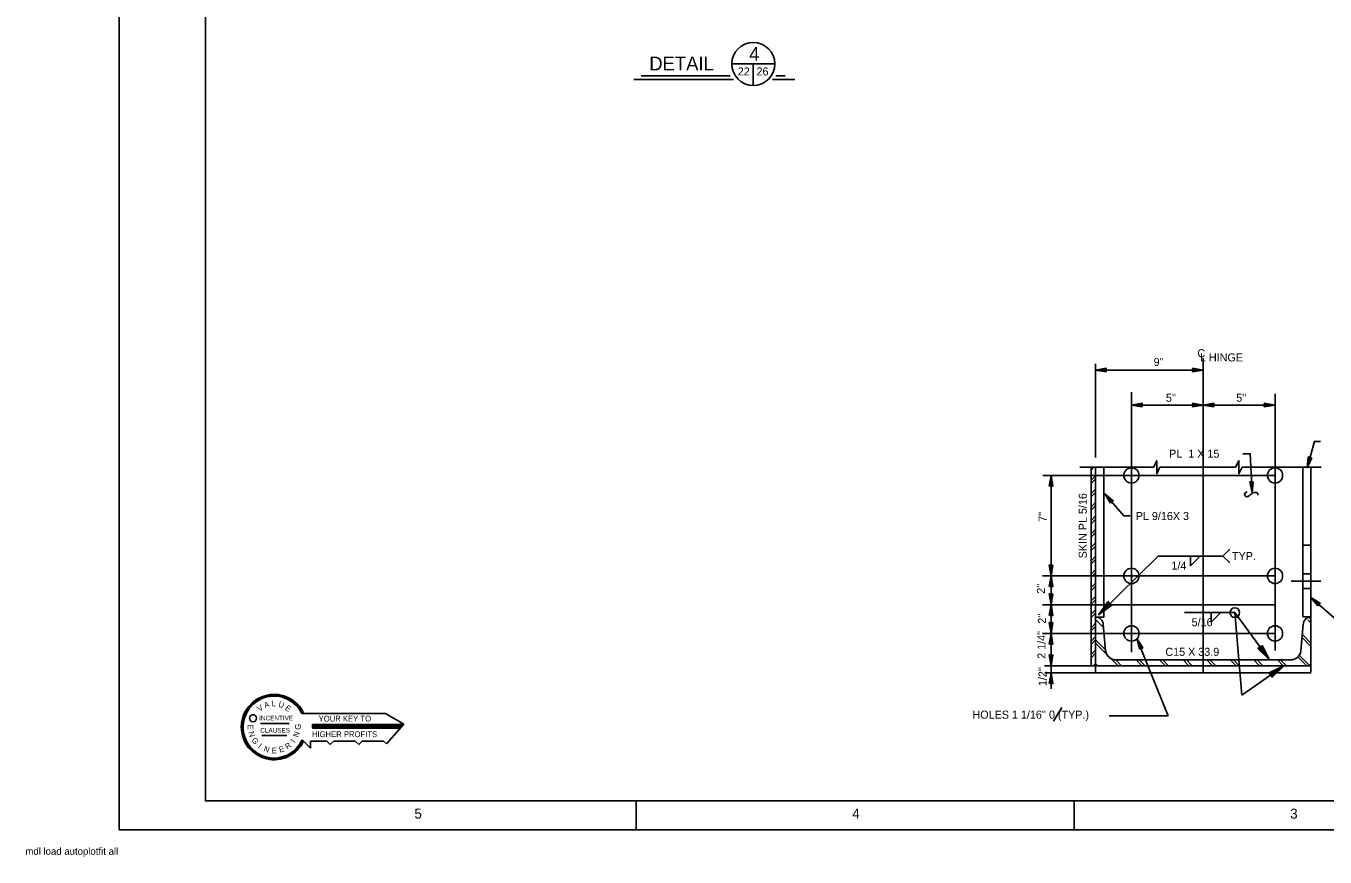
# Model space of a CAD drawing. Extents: x -0.4 to 13.5, y 0 to 9.5.
# Drawn here: x -0.42 to 7.12, y -0.03 to 4.79 of the extents above; entities that cross this region are included whole.
import ezdxf

# ---------------------------------------------------------------- set-up
doc = ezdxf.new("R2010")
doc.units = 0
for name, color, linetype in [('Level 0', 7, 'Continuous'), ('Level 1', 7, 'Continuous'), ('Level 13', 7, 'Continuous'), ('Level 25', 7, 'Continuous'), ('Level 3', 7, 'Continuous'), ('Level 44', 7, 'Continuous'), ('Level 50', 7, 'Continuous')]:
    doc.layers.add(name, color=color, linetype=linetype)

msp = doc.modelspace()

# ---------------------------------------------------------------- linework, layer by layer
at = {"layer": 'Level 0'}
for p, q in [((7.0328, 1.0761), (7.0416, 1.0849)), ((7.0375, 1.0761), (7.0416, 1.0802))]:
    msp.add_line(p, q, dxfattribs=at)
at = {"layer": 'Level 1'}
for p, q in [((5.7916, 2.7914), (6.4166, 2.7914)), ((5.9999, 2.5884), (6.4166, 2.5884)), ((6.8332, 2.5884), (6.4166, 2.5884)), ((5.6995, 2.2276), (6.1274, 2.2276)), ((6.1648, 2.2276), (6.6047, 2.2276)), ((7.1017, 2.2276), (6.6421, 2.2276)), ((7.0416, 1.6083), (6.9941, 1.6083)), ((7.0994, 1.5667), (6.926, 1.5667)), ((7.0416, 1.525), (6.9941, 1.525)), ((5.7916, 1.0761), (5.7916, 1.3594)), ((7.0416, 1.0761), (7.0416, 1.3594)), ((5.792, 1.2844), (5.7916, 1.2844)), ((7.0412, 1.2844), (7.0416, 1.2844)), ((5.5477, 0.7553), (5.5965, 0.8341)), ((1.1843, 0.7992), (1.67, 0.7992)), ((1.776, 0.7366), (1.67, 0.7992)), ((0.9443, 0.7409), (1.1107, 0.7409)), ((1.7747, 0.7349), (1.246, 0.7349)), ((1.246, 0.7349), (1.246, 0.7142)), ((1.7693, 0.7292), (1.246, 0.7292)), ((1.7647, 0.7239), (1.246, 0.7239)), ((1.7597, 0.7182), (1.246, 0.7182)), ((1.246, 0.7142), (1.756, 0.7142)), ((1.776, 0.7366), (1.675, 0.6236)), ((0.953, 0.6706), (1.097, 0.6706)), ((1.1867, 0.6459), (1.235, 0.5976)), ((1.235, 0.5976), (1.235, 0.6392)), ((1.235, 0.6392), (1.3287, 0.6392)), ((1.3287, 0.6392), (1.3493, 0.6186)), ((1.3493, 0.6186), (1.37, 0.6392)), ((1.37, 0.6392), (1.494, 0.6392)), ((1.494, 0.6392), (1.5147, 0.6186)), ((1.5147, 0.6186), (1.5353, 0.6392)), ((1.5353, 0.6392), (1.6593, 0.6392)), ((1.6593, 0.6392), (1.675, 0.6236)), ((3.125, 0.2917), (3.125, 0.125)), ((5.6667, 0.2917), (5.6667, 0.125))]:
    msp.add_line(p, q, dxfattribs=at)
for points in [[(0.125, 9.4583), (13.4583, 9.4583), (13.4583, 0.125), (0.125, 0.125)], [(0.625, 9.2917), (13.2917, 9.2917), (13.2917, 0.2917), (0.625, 0.2917)]]:
    msp.add_lwpolyline(points, close=True, dxfattribs=at)
msp.add_circle((0.9012, 0.7717), 0.0205, dxfattribs=at)
for radius, start, end in [(0.19, 24.56904, 334.42426), (0.1848, 25.30954, 334.4522), (0.1796, 26.08958, 335.59431)]:
    msp.add_arc((1.023, 0.7202), radius, start, end, dxfattribs=at)
at = {"layer": 'Level 13'}
for points in [[(6.1648, 2.2276), (6.1462, 2.1901), (6.1462, 2.265), (6.1274, 2.2276)], [(6.6421, 2.2276), (6.6234, 2.1901), (6.6234, 2.265), (6.6047, 2.2276)]]:
    msp.add_lwpolyline(points, dxfattribs=at)
at = {"layer": 'Level 25'}
for p, q in [((5.7916, 2.8265), (5.7916, 2.2847)), ((6.4166, 1.0344), (6.4166, 2.8606)), ((5.9999, 1.1539), (5.9999, 2.6626)), ((6.8332, 1.1649), (6.8332, 2.6538)), ((5.7655, 1.0761), (5.7655, 2.2276)), ((5.7655, 2.2109), (5.7822, 2.2276)), ((5.7916, 1.0344), (5.7916, 2.2276)), ((5.8391, 2.2276), (5.8391, 1.3573)), ((6.9941, 1.3594), (6.9941, 2.2297)), ((7.0416, 2.2297), (7.0416, 1.0365)), ((5.4863, 2.1802), (6.8332, 2.1802)), ((5.5334, 1.5973), (5.5334, 2.1802)), ((5.7655, 2.152), (5.7916, 2.1781)), ((5.7655, 2.1332), (5.7916, 2.1592)), ((5.7655, 2.0742), (5.7916, 2.1003)), ((5.7655, 2.0554), (5.7916, 2.0814)), ((5.7655, 1.9965), (5.7916, 2.0225)), ((5.7655, 1.9776), (5.7916, 2.0036)), ((5.7655, 1.9187), (5.7916, 1.9447)), ((5.7655, 1.8998), (5.7916, 1.9259)), ((5.7655, 1.8409), (5.7916, 1.8669)), ((5.7655, 1.822), (5.7916, 1.8481)), ((5.7655, 1.7631), (5.7916, 1.7892)), ((5.7655, 1.7443), (5.7916, 1.7703)), ((6.5306, 1.7125), (6.5704, 1.7523)), ((6.9941, 1.775), (7.0416, 1.775)), ((5.7655, 1.6853), (5.7916, 1.7114)), ((5.7655, 1.6665), (5.7916, 1.6925)), ((6.1555, 1.7125), (5.809, 1.3721)), ((6.1555, 1.7125), (6.5306, 1.7125)), ((6.343, 1.7125), (6.343, 1.6562)), ((6.343, 1.6562), (6.3989, 1.7121)), ((6.5306, 1.7125), (6.5704, 1.6727)), ((5.4841, 1.5969), (6.8332, 1.5969)), ((5.5334, 1.5973), (5.5334, 1.4306)), ((5.7655, 1.6076), (5.7916, 1.6336)), ((5.7655, 1.5887), (5.7916, 1.6147)), ((5.7655, 1.5298), (5.7916, 1.5558)), ((5.7655, 1.5109), (5.7916, 1.5369)), ((5.7655, 1.452), (5.7916, 1.478)), ((5.7655, 1.4331), (5.7916, 1.4592)), ((5.4841, 1.4302), (6.8332, 1.4302)), ((5.5334, 1.4306), (5.5334, 1.4306)), ((5.5334, 1.4306), (5.5334, 1.2639)), ((5.7655, 1.3742), (5.7916, 1.4003)), ((5.7655, 1.3553), (5.7916, 1.3814)), ((5.7916, 1.3573), (5.8391, 1.3573)), ((5.809, 1.3721), (5.809, 1.3721)), ((5.8276, 1.3903), (5.8276, 1.3903)), ((6.5998, 1.3843), (6.3074, 1.3843)), ((6.4629, 1.3849), (6.4629, 1.3286)), ((6.4629, 1.3286), (6.5188, 1.3845)), ((6.5998, 1.3843), (6.8012, 1.1094)), ((6.5998, 1.3843), (6.6412, 0.9048)), ((6.9941, 1.3594), (7.0416, 1.3594)), ((7.0416, 1.357), (7.0391, 1.3594)), ((5.7655, 1.2964), (5.7916, 1.3225)), ((5.7655, 1.2776), (5.7916, 1.3036)), ((5.7839, 1.35), (5.7839, 1.35)), ((5.85, 1.1627), (5.8358, 1.315)), ((6.9832, 1.1627), (6.9973, 1.315)), ((5.4841, 1.2636), (6.8332, 1.2636)), ((5.5334, 1.2636), (5.5334, 1.1198)), ((5.7655, 1.2186), (5.7916, 1.2447)), ((5.7655, 1.1998), (5.7916, 1.2258)), ((6.2132, 0.7853), (6.032, 1.2331)), ((5.5334, 1.0761), (5.5334, 1.1612)), ((5.7655, 1.1409), (5.7916, 1.1669)), ((5.7655, 1.122), (5.7916, 1.148)), ((5.4951, 1.0761), (5.7655, 1.0761)), ((5.5334, 1.0344), (5.5334, 1.0761)), ((5.7655, 1.0761), (5.7916, 1.0761)), ((5.7785, 1.0761), (5.7916, 1.0891)), ((5.8018, 1.0761), (5.7916, 1.0863)), ((5.7916, 1.0761), (7.0416, 1.0761)), ((5.8179, 1.0761), (6.9901, 1.0761)), ((5.9114, 1.1094), (6.9218, 1.1094)), ((6.6412, 0.9048), (6.8848, 1.0761)), ((6.7858, 1.1304), (6.7858, 1.1304)), ((6.8012, 1.1094), (6.8012, 1.1094)), ((6.8635, 1.0611), (6.8635, 1.0611)), ((6.8848, 1.0761), (6.8848, 1.0761)), ((5.4973, 1.0344), (5.7916, 1.0344)), ((5.5334, 0.9428), (5.5334, 1.0344)), ((5.7916, 1.0344), (7.0416, 1.0344)), ((5.8701, 0.7853), (6.2132, 0.7853)), ((5.7916, 0.7327), (5.7916, 0.7327))]:
    msp.add_line(p, q, dxfattribs=at)
for points in [[(5.8866, 1.4266), (5.809, 1.3721), (5.8649, 1.4487), (5.8834, 1.4298), (5.8276, 1.3903), (5.8655, 1.4423), (5.8774, 1.4302), (5.8454, 1.4079), (5.8662, 1.436), (5.8711, 1.431), (5.864, 1.4261)], [(6.7584, 1.194), (6.8012, 1.1094), (6.7334, 1.1757), (6.7548, 1.1913), (6.7858, 1.1304), (6.7398, 1.1754), (6.7536, 1.1854), (6.7711, 1.1505), (6.7462, 1.1751), (6.7519, 1.1793), (6.7557, 1.1715)], [(6.7994, 1.035), (6.8848, 1.0761), (6.8172, 1.0096), (6.802, 1.0313), (6.8635, 1.0611), (6.8176, 1.016), (6.8079, 1.0299), (6.8431, 1.0467), (6.818, 1.0224), (6.814, 1.0281), (6.8218, 1.0318)]]:
    msp.add_lwpolyline(points, dxfattribs=at)
for centre, radius in [((5.9999, 2.1802), 0.0443), ((6.8332, 2.1802), 0.0443), ((5.9999, 1.5969), 0.0443), ((6.8332, 1.5969), 0.0443), ((6.5998, 1.3843), 0.0281), ((5.9999, 1.2636), 0.0443), ((6.8332, 1.2636), 0.0443)]:
    msp.add_circle(centre, radius, dxfattribs=at)
for centre, radius, start, end in [((5.7902, 1.3138), 0.0457, 1.55293, 88.23157), ((7.043, 1.3138), 0.0457, 91.76843, 178.44707), ((5.9108, 1.1708), 0.0614, 187.587, 270.49841), ((6.9223, 1.1708), 0.0614, 269.50159, 352.413)]:
    msp.add_arc(centre, radius, start, end, dxfattribs=at)
msp.add_spline([(6.6711, 2.0842), (6.6574, 2.0746), (6.6629, 2.0576), (6.6898, 2.067), (6.7114, 2.0812), (6.7328, 2.0743), (6.7314, 2.0648)], degree=3, dxfattribs=at)
at = {"layer": 'Level 3'}
for p, q in [((3.9298, 4.5669), (3.6798, 4.5669)), ((3.8048, 4.5669), (3.8048, 4.4419)), ((3.6897, 4.4765), (3.1113, 4.4765)), ((3.6713, 4.4973), (3.1543, 4.4973)), ((4.0458, 4.4765), (3.9172, 4.4765)), ((3.9896, 4.4973), (3.9366, 4.4973)), ((7.0193, 2.2245), (7.0193, 2.2245)), ((7.024, 2.2412), (7.024, 2.2412)), ((5.8455, 2.0731), (5.8455, 2.0731)), ((5.8569, 2.0599), (5.8569, 2.0599)), ((6.6988, 2.0977), (6.6988, 2.0977)), ((6.6996, 2.0804), (6.6996, 2.0804)), ((7.0417, 1.4716), (7.0417, 1.4716)), ((7.0547, 1.4601), (7.0547, 1.4601))]:
    msp.add_line(p, q, dxfattribs=at)
for points in [[(7.0972, 2.377), (7.0615, 2.377), (7.0193, 2.2245)], [(6.6461, 2.3043), (6.6898, 2.3043), (6.6996, 2.0804)], [(7.0459, 2.2818), (7.0193, 2.2245), (7.026, 2.2873), (7.043, 2.2826), (7.024, 2.2412), (7.0285, 2.2839), (7.0394, 2.2809), (7.0284, 2.2573), (7.031, 2.2804), (7.0355, 2.2792), (7.033, 2.274)], [(6.7072, 2.1431), (6.6996, 2.0804), (6.6866, 2.1422), (6.7042, 2.1429), (6.6988, 2.0977), (6.69, 2.1397), (6.7013, 2.1402), (6.6981, 2.1143), (6.6934, 2.1371), (6.6981, 2.1373), (6.6974, 2.1316)], [(5.9915, 1.9465), (5.955, 1.9465), (5.8455, 2.0731)], [(5.8785, 2.0191), (5.8455, 2.0731), (5.8941, 2.0327), (5.8808, 2.0211), (5.8569, 2.0599), (5.8899, 2.0325), (5.8813, 2.0251), (5.8678, 2.0473), (5.8856, 2.0323), (5.8821, 2.0293), (5.8791, 2.0342)], [(7.2071, 1.3523), (7.1779, 1.3523), (7.0417, 1.4716)], [(7.0818, 1.4227), (7.0417, 1.4716), (7.0954, 1.4383), (7.0838, 1.425), (7.0547, 1.4601), (7.0912, 1.4375), (7.0837, 1.429), (7.0673, 1.4492), (7.087, 1.4368), (7.0839, 1.4333), (7.0803, 1.4377)]]:
    msp.add_lwpolyline(points, dxfattribs=at)
msp.add_circle((3.8048, 4.5669), 0.125, dxfattribs=at)
at = {"layer": 'Level 44'}
for p, q in [((5.8373, 1.2987), (5.7916, 1.3444)), ((7.0416, 1.3248), (7.0243, 1.3421)), ((7.0416, 1.3437), (7.0337, 1.3515)), ((5.8494, 1.1688), (5.7916, 1.2266)), ((5.9232, 1.0761), (5.7916, 1.2077)), ((7.0416, 1.1881), (6.9903, 1.2394)), ((7.0416, 1.207), (6.9919, 1.2566)), ((7.0358, 1.0761), (6.9741, 1.1378)), ((5.8054, 1.0761), (5.7916, 1.0899)), ((5.9421, 1.0761), (5.9088, 1.1094)), ((6.0599, 1.0761), (6.0266, 1.1094)), ((6.0788, 1.0761), (6.0455, 1.1094)), ((6.1967, 1.0761), (6.1633, 1.1094)), ((6.2155, 1.0761), (6.1822, 1.1094)), ((6.3334, 1.0761), (6.3, 1.1094)), ((6.3522, 1.0761), (6.3189, 1.1094)), ((6.4701, 1.0761), (6.4367, 1.1094)), ((6.4889, 1.0761), (6.4556, 1.1094)), ((6.6068, 1.0761), (6.5734, 1.1094)), ((6.6256, 1.0761), (6.5923, 1.1094)), ((6.7435, 1.0761), (6.7102, 1.1094)), ((6.7623, 1.0761), (6.729, 1.1094)), ((6.8802, 1.0761), (6.8469, 1.1094)), ((6.8991, 1.0761), (6.8657, 1.1094)), ((7.0169, 1.0761), (6.9657, 1.1273))]:
    msp.add_line(p, q, dxfattribs=at)
at = {"layer": 'Level 50'}
for p, q in [((5.7916, 2.7914), (5.7916, 2.7914)), ((5.8089, 2.7914), (5.8089, 2.7914)), ((6.3992, 2.7914), (6.3992, 2.7914)), ((6.4166, 2.7914), (6.4166, 2.7914)), ((5.9999, 2.5884), (5.9999, 2.5884)), ((6.0172, 2.5884), (6.0172, 2.5884)), ((6.3992, 2.5884), (6.3992, 2.5884)), ((6.4166, 2.5884), (6.4166, 2.5884)), ((6.4166, 2.5884), (6.4166, 2.5884)), ((6.4339, 2.5884), (6.4339, 2.5884)), ((6.8159, 2.5884), (6.8159, 2.5884)), ((6.8332, 2.5884), (6.8332, 2.5884)), ((5.5334, 2.1802), (5.5334, 2.1802)), ((5.5334, 2.1629), (5.5334, 2.1629)), ((5.5334, 1.6146), (5.5334, 1.6146)), ((5.5334, 1.5973), (5.5334, 1.5973)), ((5.5334, 1.5973), (5.5334, 1.5973)), ((5.5334, 1.5799), (5.5334, 1.5799)), ((5.5334, 1.4479), (5.5334, 1.4479)), ((5.5334, 1.4306), (5.5334, 1.4306)), ((5.5334, 1.4306), (5.5334, 1.4306)), ((5.5334, 1.4133), (5.5334, 1.4133)), ((5.5334, 1.2813), (5.5334, 1.2813)), ((5.5334, 1.2639), (5.5334, 1.2639)), ((5.5334, 1.2636), (5.5334, 1.2636)), ((5.5334, 1.2462), (5.5334, 1.2462)), ((6.032, 1.2331), (6.032, 1.2331)), ((6.0385, 1.217), (6.0385, 1.217)), ((5.5334, 1.0934), (5.5334, 1.0934)), ((5.5334, 1.0761), (5.5334, 1.0761)), ((5.5334, 1.0344), (5.5334, 1.0344)), ((5.5334, 1.0171), (5.5334, 1.0171))]:
    msp.add_line(p, q, dxfattribs=at)
for points in [[(5.8539, 2.7811), (5.7916, 2.7914), (5.8539, 2.8017), (5.8539, 2.7841), (5.8089, 2.7914), (5.8512, 2.7984), (5.8512, 2.7871), (5.8256, 2.7914), (5.8486, 2.7951), (5.8486, 2.7904), (5.8429, 2.7914)], [(6.3542, 2.8017), (6.4166, 2.7914), (6.3542, 2.7811), (6.3542, 2.7987), (6.3992, 2.7914), (6.3569, 2.7844), (6.3569, 2.7957), (6.3826, 2.7914), (6.3596, 2.7877), (6.3596, 2.7924), (6.3652, 2.7914)], [(6.0622, 2.5781), (5.9999, 2.5884), (6.0622, 2.5988), (6.0622, 2.5811), (6.0172, 2.5884), (6.0596, 2.5954), (6.0596, 2.5841), (6.0339, 2.5884), (6.0569, 2.5921), (6.0569, 2.5874), (6.0512, 2.5884)], [(6.3542, 2.5988), (6.4166, 2.5884), (6.3542, 2.5781), (6.3542, 2.5958), (6.3992, 2.5884), (6.3569, 2.5814), (6.3569, 2.5928), (6.3826, 2.5884), (6.3596, 2.5848), (6.3596, 2.5894), (6.3652, 2.5884)], [(6.4789, 2.5781), (6.4166, 2.5884), (6.4789, 2.5988), (6.4789, 2.5811), (6.4339, 2.5884), (6.4762, 2.5954), (6.4762, 2.5841), (6.4506, 2.5884), (6.4736, 2.5921), (6.4736, 2.5874), (6.4679, 2.5884)], [(6.7709, 2.5988), (6.8332, 2.5884), (6.7709, 2.5781), (6.7709, 2.5958), (6.8159, 2.5884), (6.7736, 2.5814), (6.7736, 2.5928), (6.7992, 2.5884), (6.7762, 2.5848), (6.7762, 2.5894), (6.7819, 2.5884)], [(5.5231, 2.1179), (5.5334, 2.1802), (5.5438, 2.1179), (5.5261, 2.1179), (5.5334, 2.1629), (5.5404, 2.1206), (5.5291, 2.1206), (5.5334, 2.1462), (5.5371, 2.1232), (5.5324, 2.1232), (5.5334, 2.1289)], [(5.5438, 1.6596), (5.5334, 1.5973), (5.5231, 1.6596), (5.5408, 1.6596), (5.5334, 1.6146), (5.5264, 1.6569), (5.5378, 1.6569), (5.5334, 1.6313), (5.5298, 1.6543), (5.5344, 1.6543), (5.5334, 1.6486)], [(5.5231, 1.5349), (5.5334, 1.5973), (5.5438, 1.5349), (5.5261, 1.5349), (5.5334, 1.5799), (5.5404, 1.5376), (5.5291, 1.5376), (5.5334, 1.5633), (5.5371, 1.5403), (5.5324, 1.5403), (5.5334, 1.5459)], [(5.5438, 1.4929), (5.5334, 1.4306), (5.5231, 1.4929), (5.5408, 1.4929), (5.5334, 1.4479), (5.5264, 1.4903), (5.5378, 1.4903), (5.5334, 1.4646), (5.5298, 1.4876), (5.5344, 1.4876), (5.5334, 1.4819)], [(5.5231, 1.3683), (5.5334, 1.4306), (5.5438, 1.3683), (5.5261, 1.3683), (5.5334, 1.4133), (5.5404, 1.3709), (5.5291, 1.3709), (5.5334, 1.3966), (5.5371, 1.3736), (5.5324, 1.3736), (5.5334, 1.3793)], [(5.5438, 1.3263), (5.5334, 1.2639), (5.5231, 1.3263), (5.5408, 1.3263), (5.5334, 1.2813), (5.5264, 1.3236), (5.5378, 1.3236), (5.5334, 1.2979), (5.5298, 1.3209), (5.5344, 1.3209), (5.5334, 1.3153)], [(5.5231, 1.2012), (5.5334, 1.2636), (5.5438, 1.2012), (5.5261, 1.2012), (5.5334, 1.2462), (5.5404, 1.2039), (5.5291, 1.2039), (5.5334, 1.2296), (5.5371, 1.2066), (5.5324, 1.2066), (5.5334, 1.2122)], [(6.0458, 1.1714), (6.032, 1.2331), (6.0649, 1.1791), (6.0486, 1.1725), (6.0385, 1.217), (6.0609, 1.1804), (6.0503, 1.1761), (6.0447, 1.2015), (6.0568, 1.1816), (6.0524, 1.1798), (6.0512, 1.1855)], [(5.5438, 1.1384), (5.5334, 1.0761), (5.5231, 1.1384), (5.5408, 1.1384), (5.5334, 1.0934), (5.5264, 1.1357), (5.5378, 1.1357), (5.5334, 1.1101), (5.5298, 1.1331), (5.5344, 1.1331), (5.5334, 1.1274)], [(5.5231, 0.9721), (5.5334, 1.0344), (5.5438, 0.9721), (5.5261, 0.9721), (5.5334, 1.0171), (5.5404, 0.9747), (5.5291, 0.9747), (5.5334, 1.0004), (5.5371, 0.9774), (5.5324, 0.9774), (5.5334, 0.9831)]]:
    msp.add_lwpolyline(points, dxfattribs=at)

# ---------------------------------------------------------------- texts
at = {"layer": 'Level 1'}
for s, rotation, p in [('V', 35.92042, (0.94, 0.8082)), ('A', 18.07309, (0.971, 0.8296)), ('U', 342.11071, (1.0453, 0.8392)), ('E', 323.92976, (1.0833, 0.8242)), ('E', 270, (0.8693, 0.7349)), ('N', 288.08209, (0.873, 0.6896)), ('N', 71.91791, (1.1633, 0.6579)), ('G', 90, (1.178, 0.7049)), ('G', 306.05369, (0.89, 0.6442)), ('I', 323.58362, (0.927, 0.6019)), ('N', 341.91791, (0.9597, 0.5809)), ('E', 18.22411, (1.0577, 0.5716)), ('R', 36.22059, (1.1013, 0.5886)), ('I', 53.58362, (1.1427, 0.6252))]:
    msp.add_text(s, height=0.0333, rotation=rotation, dxfattribs=at).set_placement(p)
for s, height, p in [('L', 0.0333, (1.0093, 0.8406)), ('INCENTIVE', 0.02667, (0.937, 0.7592)), ('YOUR KEY TO', 0.033333, (1.2817, 0.7526)), ('CLAUSES', 0.02667, (0.9433, 0.6879)), ('HIGHER PROFITS', 0.033333, (1.2427, 0.6619)), ('E', 0.0333, (1.0087, 0.5679)), ('5', 0.0584, (1.8378, 0.189)), ('4', 0.0584, (4.3795, 0.189)), ('3', 0.0584, (6.9211, 0.1889))]:
    msp.add_text(s, height=height, dxfattribs=at).set_placement(p)
at = {"layer": 'Level 25'}
for s, height, p in [('C', 0.0467, (6.3825, 2.8652)), ('L HINGE', 0.0467, (6.3975, 2.8412)), ("9''", 0.0467, (6.1285, 2.8147)), ("5''", 0.0467, (6.2, 2.6073)), ("5''", 0.0467, (6.6079, 2.6073)), ('PL  1 X 15', 0.0467, (6.2184, 2.2828)), ('PL 9/16X 3', 0.0467, (6.0248, 1.9211)), ('TYP.', 0.0467, (6.5835, 1.6891)), ('1/4', 0.0467, (6.232, 1.6331)), ('5/16', 0.0467, (6.3491, 1.305)), ('C15 X 33.9', 0.0467, (6.1967, 1.1335)), ("HOLES 1 1/16'' 0 (TYP.)", 0.046698, (5.0772, 0.7689)), ('mdl load autoplotfit all', 0.041667, (-0.4204, -0.0208))]:
    msp.add_text(s, height=height, dxfattribs=at).set_placement(p)
for s, height, p in [('SKIN PL 5/16', 0.046698, (5.7405, 1.699)), ("7''", 0.0467, (5.507, 1.9106)), ("2''", 0.0467, (5.4978, 1.4936)), ("2''", 0.0467, (5.5033, 1.3201)), ('2 1/4"', 0.0467, (5.5009, 1.1161)), ("1/2''", 0.0467, (5.507, 0.9578))]:
    msp.add_text(s, height=height, rotation=90, dxfattribs=at).set_placement(p)
at = {"layer": 'Level 3'}
for s, height, p in [('DETAIL', 0.08, (3.2011, 4.5293)), ('4', 0.08, (3.7807, 4.5848)), ('22', 0.04679, (3.7148, 4.4998)), ('26', 0.04679, (3.8235, 4.4998))]:
    msp.add_text(s, height=height, dxfattribs=at).set_placement(p)

doc.saveas('drawing.dxf')
